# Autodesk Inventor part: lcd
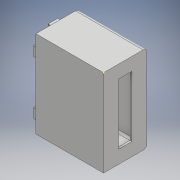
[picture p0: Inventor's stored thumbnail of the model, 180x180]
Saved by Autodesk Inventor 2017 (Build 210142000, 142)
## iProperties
Created: 2016-11
Part Number: lcd
Material: Generic
Document SubType Name: Modeling
Designer: mivas
Density: 1 g/cm^3
Appearance: Default
Author: mivas
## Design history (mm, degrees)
sketch "Sketch1"
  geometry: L1 (0, 0)-(45, 0); L2 (45, 0)-(45, -90); L3 (45, -90)-(0, -90); L4 (0, -90)-(0, 0)
  constraints: 8 end point, 2 parallel, 1 horizontal, 1 perpendicular
  dimensions: "d0" = 90 distance of L1.end L2.end; "d1" = 45 distance of L2.end L3.end
extrude "Extrusion1" new body sketch "Sketch1" distance "d2" = 70; taper "d3" = 0 deg
sketch "Sketch2"
  geometry: 1 further point
sketch "Sketch3"
  geometry: L1 (13.331, 29.439)-(76.331, 29.439); L2 (76.331, 29.439)-(76.331, 15.439); L3 (76.331, 15.439)-(13.331, 15.439); L4 (13.331, 15.439)-(13.331, 29.439); L5 (90, 45)-(0, 45) reference; L6 (0, 0)-(90, 0) reference; L7 (0, 45)-(0, 0) reference; L8 (90, 0)-(90, 45) reference; 8 further points
  constraints: 8 end point, 8 midpoint, 2 parallel, 1 horizontal, 1 perpendicular
  dimensions: "d4" = 63 distance of L1.start L1.end; "d5" = 14 distance of L1.end L2.end; "d6" = 13.33112 horizontal distance of point (0, 22.5) point (13.331, 22.439)
extrude "Extrusion2" cut sketch "Sketch3" distance "d7" = 75; taper "d8" = 0 deg
sketch "Sketch4"
  geometry: L1 (-85, 42)-(-5, 42); L2 (-3, 40)-(-3, 5); L3 (-5, 3)-(-85, 3); L4 (-87, 5)-(-87, 40); L5 (-90, 0)-(-90, 45) reference; L6 (0, 45)-(0, 0) reference; L7 (-90, 45)-(0, 45) reference; L8 (0, 0)-(-90, 0) reference; A1 r 2 centre (-5, 40) between (-3, 40) and (-5, 42); A2 r 2 centre (-5, 5) between (-5, 3) and (-3, 5); A3 r 2 centre (-85, 5) between (-87, 5) and (-85, 3); A4 r 2 centre (-85, 40) between (-85, 42) and (-87, 40)
  constraints: 8 end point, 8 point on circle, 8 tangent, 4 centre point, 3 equal radius, 2 parallel, 1 horizontal, 1 perpendicular
  dimensions: "d9" = 3 distance between parallel lines of L5 L4; "d10" = 3 distance between parallel lines of L6 L2; "d11" = 3 distance between parallel lines of L7 L1; "d12" = 3 distance between parallel lines of L8 L3; "d13" = 2 radius of A1 (derived)
extrude "Extrusion3" cut sketch "Sketch4" distance "d14" = 68; taper "d15" = 0 deg
sketch "Sketch5"
  geometry: L1 (-87, 5)-(-87, 40) reference; L2 (-87, 33.128)-(-78.128, 42); L3 (-85, 42)-(-5, 42) reference; L4 (-3, 40)-(-3, 5) reference; L5 (-3, 33.128)-(-11.872, 42); L6 (-5, 3)-(-85, 3) reference; L7 (-78.128, 3)-(-87, 11.872); L8 (-11.872, 3)-(-3, 11.872); L9 (-87, 33.128)-(-87, 42); L10 (-87, 42)-(-78.128, 42); L11 (-87, 11.872)-(-87, 3); L12 (-87, 3)-(-78.128, 3); L13 (-11.872, 42)-(-3, 42); L14 (-3, 42)-(-3, 33.128); L15 (-3, 11.872)-(-3, 3); L16 (-3, 3)-(-11.872, 3); 1 further point
  constraints: 24 end point, 10 point on line, 3 collinear, 2 vertical, 1 perpendicular
  dimensions: "d16" = 8.87205 horizontal distance of L2.start L2.end; "d17" = 45 deg angle of L1 L2; "d18" = 8.87205 horizontal distance of L5.start L5.end; "d19" = 135 deg angle of L3 L5; "d20" = 135 deg angle of L6 L7; "d21" = 135 deg angle of L1 L7 (derived); "d22" = 12.54697 distance of L7.start L7.end; "d23" = 12.54697 distance of L8.start L8.end; "d24" = 135 deg angle of L6 L8
extrude "Extrusion4" join sketch "Sketch5" distance "d25" = 5; taper "d26" = 0 deg
fillet "Fillet1" dims "d27" = 4
sketch "Sketch6"
  geometry: L1 (70, 0)-(0, 0) reference; L2 (0, 82)-(70, 82) reference; L3 (0, 81)-(0, 1) reference; L4 (70, 9.331)-(70, 72.331) reference; C1 r 3.5 at (35, 16.767); C2 r 3.5 at (35, 40.767); C3 r 3.5 at (35, 64.767); 5 further points
  constraints: 4 midpoint, 3 centre point
  dimensions: "d28" = 7 diameter of C1; "d29" = 7 diameter of C2; "d30" = 7 diameter of C3; "d31" = 24 distance of C1.centre C2.centre; "d32" = 24 distance of C3.centre C2.centre
extrude "Extrusion5" cut sketch "Sketch6" distance "d33" = 5; taper "d34" = 0 deg
sketch "Sketch7"
  geometry: L1 (-77.949, 44.5)-(-67.949, 44.5); L2 (-67.949, 44.5)-(-67.949, 42.5); L3 (-67.949, 42.5)-(-77.949, 42.5); L4 (-77.949, 42.5)-(-77.949, 44.5); L5 (-86, 45)-(-4, 45) reference; L6 (-22.393, 42.5)-(-22.393, 44.5); L7 (-12.393, 42.5)-(-22.393, 42.5); L8 (-12.393, 44.5)-(-12.393, 42.5); L9 (-22.393, 44.5)-(-12.393, 44.5); L10 (-77.949, 0.564)-(-77.949, 2.564); L11 (-67.949, 0.564)-(-77.949, 0.564); L12 (-67.949, 2.564)-(-67.949, 0.564); L13 (-77.949, 2.564)-(-67.949, 2.564); L14 (-22.393, 0.616)-(-22.393, 2.616); L15 (-12.393, 0.616)-(-22.393, 0.616); L16 (-12.393, 2.616)-(-12.393, 0.616); L17 (-22.393, 2.616)-(-12.393, 2.616); A1 r 4 centre (-86, 41) between (-86, 45) and (-90, 41) reference; A2 r 4 centre (-4, 41) between (0, 41) and (-4, 45) reference; 1 further point
  constraints: 32 end point, 8 parallel, 4 horizontal, 4 perpendicular
  dimensions: "d36" = 0.5 distance between parallel lines of L5 L1; "d37" = 2 distance between parallel lines of L3 L1; "d38" = 10 distance between parallel lines of L2 L4 (derived); "d39" = 2 distance of L3.end L1.start (derived); "d40" = 8.05128 distance from line of A1.centre L4; "d41" = 63.94872 distance from line of A2.centre L2; "d42" = 2 distance between parallel lines of L7 L9; "d43" = 10 distance between parallel lines of L8 L6 (derived); "d44" = 2 distance of L6.start L6.end (derived); "d45" = 2 distance between parallel lines of L11 L13; "d46" = 10 distance between parallel lines of L12 L10 (derived); "d47" = 2 distance of L10.start L10.end (derived); "d48" = 2 distance between parallel lines of L15 L17; "d49" = 10 distance between parallel lines of L16 L14 (derived); "d50" = 2 distance of L14.start L14.end (derived)
extrude "Extrusion6" join sketch "Sketch7" distance "d51" = 3; taper "d52" = 0 deg
sketch "Sketch8"
  geometry: L1 (-89.5, 25.483)-(-87.5, 25.483); L2 (-87.5, 25.483)-(-87.5, 15.483); L3 (-87.5, 15.483)-(-89.5, 15.483); L4 (-89.5, 15.483)-(-89.5, 25.483); L5 (-90, 41)-(-90, 0) reference; L6 (-2.54, 25.637)-(-0.54, 25.637); L7 (-0.54, 25.637)-(-0.54, 15.637); L8 (-0.54, 15.637)-(-2.54, 15.637); L9 (-2.54, 15.637)-(-2.54, 25.637); L10 (-90, 0)-(0, 0) reference; L11 (-3, 40)-(-3, 5) reference; A1 r 4 centre (-86, 41) between (-86, 45) and (-90, 41) reference
  constraints: 16 end point, 4 parallel, 2 horizontal, 2 perpendicular
  dimensions: "d53" = 10 distance of L3.end L1.start; "d54" = 0.5 distance between parallel lines of L5 L4; "d55" = 2 distance between parallel lines of L2 L4; "d56" = 15.51694 distance from line of A1.centre L1; "d57" = 10 distance of L8.end L6.start; "d58" = 2 distance between parallel lines of L7 L9; "d59" = 15.63698 distance between parallel lines of L10 L8; "d60" = 0.4598 distance between parallel lines of L11 L9; "d61" = 2 distance of L1.start L1.end (derived)
extrude "Extrusion7" join sketch "Sketch8" distance "d62" = 3; taper "d63" = 0 deg
body "Solid1"
